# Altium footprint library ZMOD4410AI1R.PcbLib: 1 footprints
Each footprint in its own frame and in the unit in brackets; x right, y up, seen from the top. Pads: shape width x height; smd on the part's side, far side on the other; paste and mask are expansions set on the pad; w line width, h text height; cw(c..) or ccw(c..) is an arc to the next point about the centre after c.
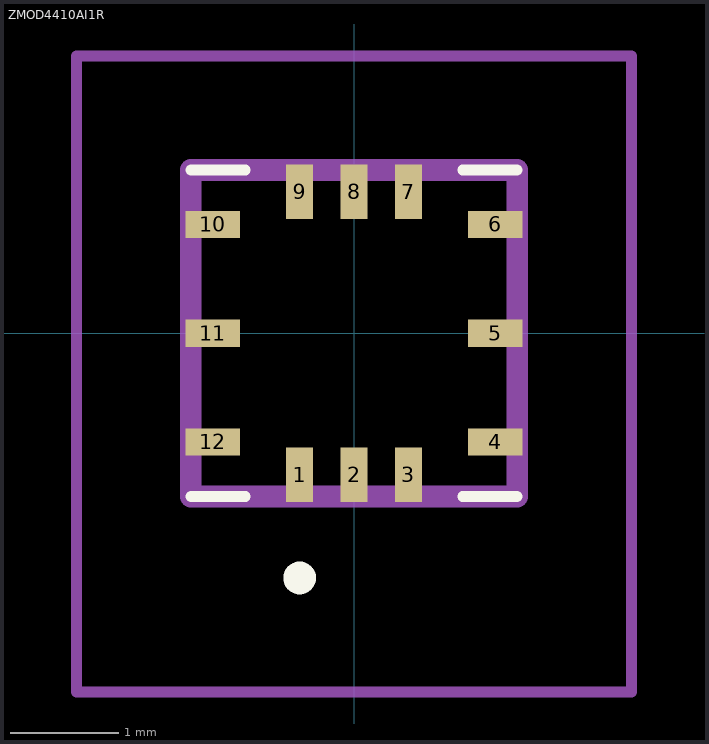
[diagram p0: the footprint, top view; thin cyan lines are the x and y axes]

## ZMOD4410AI1R [mm]
pads (12):
  rect 0.25x0.5 smd: 1(-0.5,-1.3) 2(0,-1.3) 3(0.5,-1.3) 7(0.5,1.3) 8(0,1.3) 9(-0.5,1.3)
  rect 0.5x0.25 smd: 4(1.3,-1) 5(1.3,0) 6(1.3,1) 10(-1.3,1) 11(-1.3,0) 12(-1.3,-1)
Top Overlay:
  lines w0.1: -1.5,-1.5 -1,-1.5 ; -1.5,-1.5 -1,-1.5 ; -1.5,-1.5 -1.5,-1.5 ; -1.5,1.5 -1,1.5 ; -1.5,1.5 -1,1.5 ; -1.5,1.5 -1.5,1.5 ; -1,-1.5 -1,-1.5 ; -1,1.5 -1,1.5 ; 1,-1.5 1.5,-1.5 ; 1,-1.5 1.5,-1.5 ; 1,-1.5 1,-1.5 ; 1,1.5 1.5,1.5 ; 1,1.5 1.5,1.5 ; 1,1.5 1,1.5 ; 1.5,-1.5 1.5,-1.5 ; 1.5,1.5 1.5,1.5
  lines w0.2: -0.5,-2.3 -0.5,-2.3 ; -0.5,-2.3 ccw(c-0.5,-2.25) -0.5,-2.2 ; -0.5,-2.3 cw(c-0.5,-2.25) -0.5,-2.2 ; -0.5,-2.3 -0.5,-2.3 ; -0.5,-2.3 ccw(c-0.5,-2.25) -0.5,-2.2 ; -0.5,-2.2 -0.5,-2.2
Mechanical 15:
  lines w0.2: -1.5,-1.5 1.5,-1.5 1.5,1.5 -1.5,1.5 -1.5,-1.5
Mechanical 20:
  lines w0.1: -2.55,-3.3 2.55,-3.3 2.55,2.55 -2.55,2.55 -2.55,-3.3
